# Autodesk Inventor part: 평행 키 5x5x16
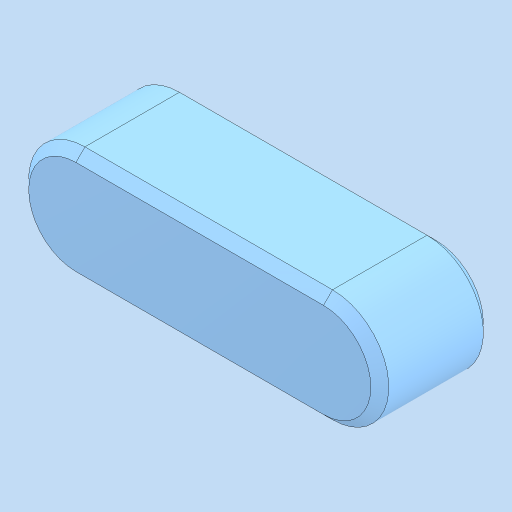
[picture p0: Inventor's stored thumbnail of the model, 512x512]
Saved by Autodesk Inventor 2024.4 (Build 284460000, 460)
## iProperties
Created: 2026-07
Part Number: 평행 키 5x5x16
Material: 강철, 연강
Description: 키 및 해당 키홈
Document SubType Name: Modeling
Designer: home
Density: 7.85 g/cm^3
Appearance: 기본값
Author: jhkim
Sending System: Autodesk Inventor 2027
Preprocessor: ST-DEVELOPER v20.1
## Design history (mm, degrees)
feature "Solid1"
node "솔리드1"
